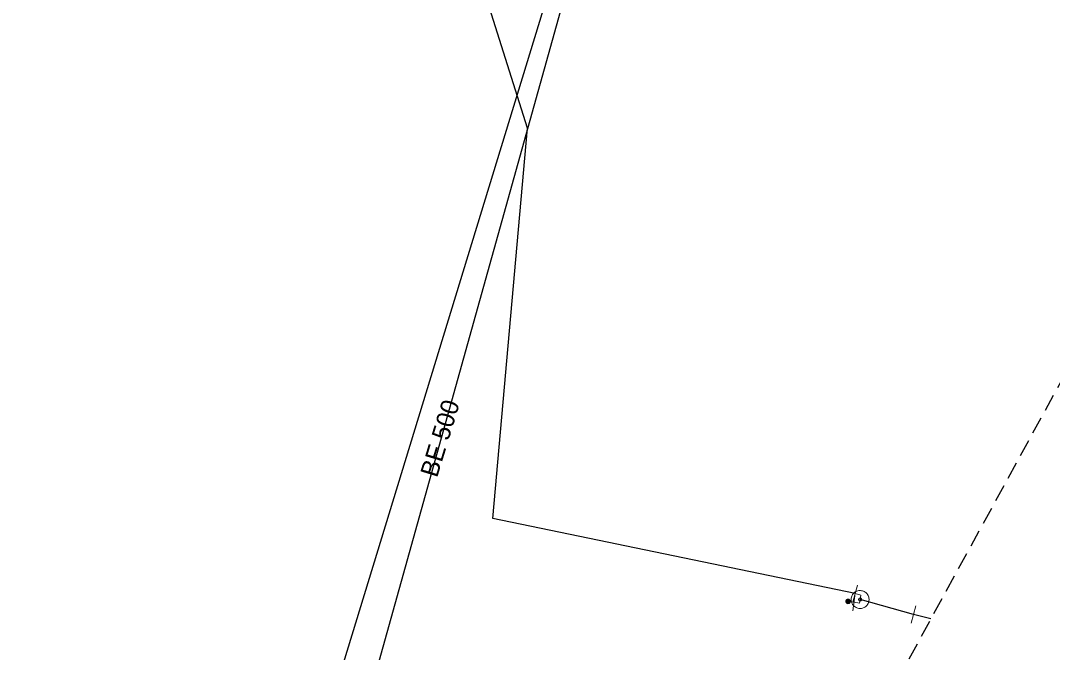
# Model space of a CAD drawing. Extents: x -725153 to -724843, y -978146 to -977794.
# Drawn here: x -724958 to -724900.4, y -978087.1 to -978051.8 of the extents above; entities that cross this region are included whole.
import ezdxf

# ---------------------------------------------------------------- set-up
doc = ezdxf.new("R2010")
doc.units = 0
doc.header["$LTSCALE"] = 0.32
doc.linetypes.add('MEDIUM_DASHED', pattern=[4.5, 3, -1.5])
doc.layers.add('1', color=7, linetype='Continuous')
for name, color, linetype, lineweight in [('14', 7, 'Continuous', 25), ('17', 7, 'Continuous', 25), ('34', 7, 'Continuous', 13), ('47', 7, 'Continuous', 13), ('63', 7, 'MEDIUM_DASHED', 25), ('9', 7, 'Continuous', 13)]:
    doc.layers.add(name, color=color, linetype=linetype, lineweight=lineweight)

msp = doc.modelspace()

# ---------------------------------------------------------------- linework, layer by layer
at = {"layer": '14'}
for p, q in [((-724927.944, -978048.326), (-724943.585, -978099.465)), ((-724927.274, -978049.14), (-724941.044, -978098.504))]:
    msp.add_line(p, q, dxfattribs=at)
at = {"layer": '14', "lineweight": 13}
for points in [[(-724911.375, -978083.783), (-724911.07, -978083.868), (-724911.108, -978084.11)], [(-724911.108, -978084.11), (-724911.147, -978084.309), (-724911.448, -978084.252), (-724911.778, -978084.216)]]:
    msp.add_lwpolyline(points, dxfattribs=at)
at = {"layer": '17'}
for points in [[(-724911.375, -978083.783), (-724931.616, -978079.579), (-724929.686, -978057.78), (-724935.405, -978039.66), (-724932.296, -977965.921)], [(-724907.151, -978085.183), (-724908.121, -978084.951), (-724911.108, -978084.11)]]:
    msp.add_lwpolyline(points, dxfattribs=at)
at = {"layer": '34'}
for p, q in [((-724911.245, -978083.3), (-724911.505, -978084.265)), ((-724911.379, -978083.756), (-724911.517, -978084.747)), ((-724907.986, -978084.469), (-724908.256, -978085.432))]:
    msp.add_line(p, q, dxfattribs=at)
at = {"layer": '47'}
for points in [[(-724910.608, -978084.137), (-724910.608, -978084.085), (-724910.613, -978084.033), (-724910.625, -978083.982), (-724910.64, -978083.932), (-724910.661, -978083.884), (-724910.688, -978083.838), (-724910.719, -978083.797), (-724910.753, -978083.758), (-724910.792, -978083.722), (-724910.834, -978083.691), (-724910.879, -978083.664), (-724910.927, -978083.644), (-724910.977, -978083.627), (-724911.028, -978083.616), (-724911.08, -978083.61), (-724911.132, -978083.61), (-724911.184, -978083.615), (-724911.236, -978083.627), (-724911.285, -978083.642), (-724911.333, -978083.663), (-724911.379, -978083.69), (-724911.421, -978083.721), (-724911.46, -978083.755), (-724911.496, -978083.794), (-724911.526, -978083.836), (-724911.553, -978083.881), (-724911.574, -978083.929), (-724911.59, -978083.979), (-724911.601, -978084.03), (-724911.607, -978084.082), (-724911.607, -978084.134), (-724911.602, -978084.186), (-724911.591, -978084.238), (-724911.575, -978084.287), (-724911.554, -978084.335), (-724911.528, -978084.381), (-724911.497, -978084.423), (-724911.463, -978084.462), (-724911.423, -978084.498), (-724911.381, -978084.528), (-724911.336, -978084.555), (-724911.289, -978084.576), (-724911.238, -978084.592), (-724911.187, -978084.603), (-724911.135, -978084.609), (-724911.083, -978084.609), (-724911.031, -978084.604), (-724910.98, -978084.593), (-724910.93, -978084.577), (-724910.882, -978084.556), (-724910.836, -978084.53), (-724910.795, -978084.499), (-724910.756, -978084.465), (-724910.72, -978084.425), (-724910.689, -978084.383), (-724910.662, -978084.338), (-724910.642, -978084.291), (-724910.625, -978084.24), (-724910.614, -978084.189)], [(-724911.026, -978084.114), (-724911.025, -978084.105), (-724911.027, -978084.097), (-724911.028, -978084.089), (-724911.031, -978084.081), (-724911.034, -978084.072), (-724911.039, -978084.065), (-724911.044, -978084.058), (-724911.049, -978084.052), (-724911.056, -978084.046), (-724911.063, -978084.041), (-724911.07, -978084.036), (-724911.078, -978084.033), (-724911.086, -978084.031), (-724911.094, -978084.028), (-724911.103, -978084.028), (-724911.112, -978084.027), (-724911.12, -978084.029), (-724911.128, -978084.03), (-724911.136, -978084.033), (-724911.145, -978084.036), (-724911.152, -978084.041), (-724911.159, -978084.046), (-724911.165, -978084.051), (-724911.172, -978084.058), (-724911.176, -978084.065), (-724911.181, -978084.072), (-724911.184, -978084.08), (-724911.186, -978084.088), (-724911.189, -978084.096), (-724911.189, -978084.105), (-724911.19, -978084.114), (-724911.188, -978084.122), (-724911.187, -978084.13), (-724911.184, -978084.138), (-724911.181, -978084.147), (-724911.177, -978084.154), (-724911.171, -978084.161), (-724911.166, -978084.167), (-724911.159, -978084.174), (-724911.152, -978084.178), (-724911.145, -978084.183), (-724911.137, -978084.186), (-724911.129, -978084.188), (-724911.121, -978084.191), (-724911.112, -978084.191), (-724911.103, -978084.192), (-724911.095, -978084.19), (-724911.087, -978084.189), (-724911.079, -978084.186), (-724911.07, -978084.183), (-724911.063, -978084.179), (-724911.056, -978084.173), (-724911.05, -978084.168), (-724911.044, -978084.161), (-724911.039, -978084.154), (-724911.034, -978084.147), (-724911.031, -978084.139), (-724911.029, -978084.131), (-724911.026, -978084.123)]]:
    msp.add_lwpolyline(points, close=True, dxfattribs=at)
at = {"layer": '63'}
msp.add_lwpolyline([(-725126.038, -977904.704), (-725126.038, -977794.451), (-724874.829, -977812.594), (-724855.29, -977827.945), (-724842.73, -977919.358), (-724859.477, -977998.21), (-724911.114, -978092.413), (-724961.356, -978146.144), (-725152.554, -978126.605)], close=True, dxfattribs=at)
at = {"layer": '9'}
for points in [[(-724911.904, -978084.216), (-724911.904, -978084.229), (-724911.902, -978084.242), (-724911.899, -978084.255), (-724911.894, -978084.267), (-724911.888, -978084.279), (-724911.881, -978084.29), (-724911.873, -978084.3), (-724911.863, -978084.31), (-724911.853, -978084.318), (-724911.842, -978084.325), (-724911.83, -978084.331), (-724911.818, -978084.336), (-724911.805, -978084.339), (-724911.792, -978084.341), (-724911.779, -978084.343), (-724911.766, -978084.342), (-724911.753, -978084.34), (-724911.74, -978084.337), (-724911.728, -978084.332), (-724911.716, -978084.326), (-724911.705, -978084.319), (-724911.695, -978084.311), (-724911.685, -978084.301), (-724911.677, -978084.291), (-724911.67, -978084.28), (-724911.664, -978084.268), (-724911.659, -978084.256), (-724911.656, -978084.243), (-724911.654, -978084.23), (-724911.652, -978084.217), (-724911.653, -978084.204), (-724911.655, -978084.191), (-724911.658, -978084.178), (-724911.663, -978084.166), (-724911.669, -978084.154), (-724911.676, -978084.143), (-724911.684, -978084.133), (-724911.694, -978084.123), (-724911.704, -978084.115), (-724911.715, -978084.108), (-724911.727, -978084.102), (-724911.739, -978084.097), (-724911.752, -978084.094), (-724911.765, -978084.092), (-724911.778, -978084.091), (-724911.791, -978084.091), (-724911.804, -978084.093), (-724911.817, -978084.096), (-724911.829, -978084.101), (-724911.841, -978084.107), (-724911.852, -978084.114), (-724911.862, -978084.122), (-724911.872, -978084.132), (-724911.88, -978084.142), (-724911.887, -978084.153), (-724911.893, -978084.165), (-724911.898, -978084.177), (-724911.901, -978084.19), (-724911.903, -978084.203)], [(-724911.884, -978084.216), (-724911.885, -978084.227), (-724911.883, -978084.238), (-724911.88, -978084.249), (-724911.876, -978084.259), (-724911.871, -978084.269), (-724911.865, -978084.278), (-724911.858, -978084.287), (-724911.85, -978084.295), (-724911.841, -978084.302), (-724911.832, -978084.308), (-724911.822, -978084.313), (-724911.812, -978084.317), (-724911.801, -978084.32), (-724911.79, -978084.323), (-724911.779, -978084.323), (-724911.768, -978084.323), (-724911.757, -978084.321), (-724911.746, -978084.318), (-724911.736, -978084.314), (-724911.726, -978084.309), (-724911.717, -978084.303), (-724911.708, -978084.296), (-724911.7, -978084.288), (-724911.693, -978084.279), (-724911.687, -978084.27), (-724911.682, -978084.26), (-724911.678, -978084.25), (-724911.675, -978084.239), (-724911.673, -978084.228), (-724911.672, -978084.217), (-724911.672, -978084.206), (-724911.674, -978084.195), (-724911.677, -978084.184), (-724911.681, -978084.174), (-724911.686, -978084.164), (-724911.692, -978084.155), (-724911.699, -978084.146), (-724911.707, -978084.138), (-724911.716, -978084.131), (-724911.725, -978084.125), (-724911.735, -978084.12), (-724911.745, -978084.116), (-724911.756, -978084.113), (-724911.767, -978084.111), (-724911.778, -978084.111), (-724911.789, -978084.11), (-724911.8, -978084.112), (-724911.811, -978084.115), (-724911.821, -978084.119), (-724911.831, -978084.124), (-724911.84, -978084.13), (-724911.849, -978084.137), (-724911.857, -978084.145), (-724911.864, -978084.154), (-724911.87, -978084.163), (-724911.875, -978084.173), (-724911.879, -978084.183), (-724911.882, -978084.194), (-724911.884, -978084.205)], [(-724911.865, -978084.216), (-724911.865, -978084.225), (-724911.864, -978084.234), (-724911.861, -978084.243), (-724911.858, -978084.251), (-724911.854, -978084.259), (-724911.849, -978084.267), (-724911.843, -978084.274), (-724911.837, -978084.28), (-724911.83, -978084.286), (-724911.822, -978084.291), (-724911.814, -978084.295), (-724911.806, -978084.298), (-724911.797, -978084.301), (-724911.788, -978084.302), (-724911.779, -978084.304), (-724911.77, -978084.303), (-724911.761, -978084.302), (-724911.752, -978084.299), (-724911.744, -978084.296), (-724911.736, -978084.292), (-724911.728, -978084.287), (-724911.721, -978084.281), (-724911.715, -978084.275), (-724911.709, -978084.268), (-724911.704, -978084.26), (-724911.7, -978084.252), (-724911.697, -978084.244), (-724911.694, -978084.235), (-724911.693, -978084.226), (-724911.691, -978084.217), (-724911.692, -978084.208), (-724911.693, -978084.199), (-724911.696, -978084.19), (-724911.699, -978084.182), (-724911.703, -978084.174), (-724911.708, -978084.166), (-724911.714, -978084.159), (-724911.72, -978084.153), (-724911.727, -978084.147), (-724911.735, -978084.142), (-724911.743, -978084.138), (-724911.751, -978084.135), (-724911.76, -978084.132), (-724911.769, -978084.131), (-724911.778, -978084.13), (-724911.787, -978084.13), (-724911.796, -978084.131), (-724911.805, -978084.134), (-724911.813, -978084.137), (-724911.821, -978084.141), (-724911.829, -978084.146), (-724911.836, -978084.152), (-724911.842, -978084.158), (-724911.848, -978084.165), (-724911.853, -978084.173), (-724911.857, -978084.181), (-724911.86, -978084.189), (-724911.863, -978084.198), (-724911.864, -978084.207)], [(-724911.845, -978084.216), (-724911.845, -978084.223), (-724911.844, -978084.23), (-724911.843, -978084.237), (-724911.84, -978084.243), (-724911.837, -978084.249), (-724911.833, -978084.255), (-724911.829, -978084.261), (-724911.824, -978084.266), (-724911.818, -978084.27), (-724911.812, -978084.274), (-724911.806, -978084.277), (-724911.8, -978084.28), (-724911.793, -978084.281), (-724911.786, -978084.284), (-724911.779, -978084.284), (-724911.772, -978084.284), (-724911.765, -978084.282), (-724911.758, -978084.281), (-724911.752, -978084.278), (-724911.745, -978084.275), (-724911.74, -978084.271), (-724911.734, -978084.267), (-724911.729, -978084.262), (-724911.725, -978084.256), (-724911.721, -978084.25), (-724911.718, -978084.244), (-724911.715, -978084.238), (-724911.713, -978084.231), (-724911.712, -978084.224), (-724911.711, -978084.217), (-724911.711, -978084.21), (-724911.712, -978084.203), (-724911.714, -978084.196), (-724911.717, -978084.19), (-724911.72, -978084.183), (-724911.724, -978084.178), (-724911.728, -978084.172), (-724911.733, -978084.167), (-724911.739, -978084.163), (-724911.744, -978084.159), (-724911.751, -978084.156), (-724911.757, -978084.153), (-724911.764, -978084.151), (-724911.771, -978084.15), (-724911.778, -978084.15), (-724911.785, -978084.15), (-724911.792, -978084.15), (-724911.799, -978084.152), (-724911.805, -978084.155), (-724911.811, -978084.158), (-724911.817, -978084.162), (-724911.823, -978084.166), (-724911.828, -978084.171), (-724911.832, -978084.177), (-724911.836, -978084.182), (-724911.839, -978084.189), (-724911.842, -978084.195), (-724911.843, -978084.202), (-724911.845, -978084.209)], [(-724911.825, -978084.216), (-724911.825, -978084.221), (-724911.825, -978084.226), (-724911.824, -978084.231), (-724911.822, -978084.235), (-724911.82, -978084.24), (-724911.817, -978084.244), (-724911.814, -978084.247), (-724911.81, -978084.251), (-724911.807, -978084.254), (-724911.803, -978084.257), (-724911.798, -978084.259), (-724911.794, -978084.261), (-724911.789, -978084.262), (-724911.784, -978084.264), (-724911.779, -978084.264), (-724911.774, -978084.264), (-724911.769, -978084.263), (-724911.764, -978084.262), (-724911.76, -978084.26), (-724911.755, -978084.258), (-724911.751, -978084.255), (-724911.747, -978084.252), (-724911.744, -978084.248), (-724911.741, -978084.245), (-724911.738, -978084.241), (-724911.736, -978084.236), (-724911.734, -978084.232), (-724911.733, -978084.227), (-724911.732, -978084.222), (-724911.731, -978084.217), (-724911.731, -978084.212), (-724911.732, -978084.207), (-724911.733, -978084.202), (-724911.735, -978084.198), (-724911.737, -978084.193), (-724911.74, -978084.189), (-724911.743, -978084.185), (-724911.746, -978084.182), (-724911.75, -978084.179), (-724911.754, -978084.176), (-724911.759, -978084.174), (-724911.763, -978084.172), (-724911.768, -978084.171), (-724911.773, -978084.17), (-724911.778, -978084.17), (-724911.783, -978084.17), (-724911.788, -978084.171), (-724911.793, -978084.171), (-724911.797, -978084.173), (-724911.802, -978084.175), (-724911.806, -978084.178), (-724911.809, -978084.181), (-724911.813, -978084.184), (-724911.816, -978084.188), (-724911.819, -978084.192), (-724911.821, -978084.197), (-724911.823, -978084.201), (-724911.824, -978084.206), (-724911.825, -978084.211)], [(-724911.805, -978084.216), (-724911.805, -978084.219), (-724911.806, -978084.222), (-724911.805, -978084.224), (-724911.804, -978084.227), (-724911.803, -978084.23), (-724911.801, -978084.232), (-724911.799, -978084.234), (-724911.797, -978084.236), (-724911.795, -978084.238), (-724911.793, -978084.24), (-724911.79, -978084.242), (-724911.787, -978084.243), (-724911.785, -978084.243), (-724911.782, -978084.244), (-724911.779, -978084.244), (-724911.776, -978084.244), (-724911.773, -978084.244), (-724911.77, -978084.243), (-724911.768, -978084.242), (-724911.765, -978084.241), (-724911.763, -978084.239), (-724911.76, -978084.237), (-724911.758, -978084.235), (-724911.757, -978084.233), (-724911.755, -978084.231), (-724911.754, -978084.228), (-724911.752, -978084.225), (-724911.752, -978084.223), (-724911.751, -978084.22), (-724911.75, -978084.217), (-724911.751, -978084.214), (-724911.751, -978084.211), (-724911.752, -978084.208), (-724911.753, -978084.206), (-724911.754, -978084.203), (-724911.756, -978084.201), (-724911.757, -978084.198), (-724911.759, -978084.196), (-724911.762, -978084.195), (-724911.764, -978084.193), (-724911.767, -978084.192), (-724911.769, -978084.191), (-724911.772, -978084.19), (-724911.775, -978084.19), (-724911.778, -978084.189), (-724911.781, -978084.19), (-724911.784, -978084.189), (-724911.786, -978084.191), (-724911.789, -978084.191), (-724911.792, -978084.192), (-724911.794, -978084.194), (-724911.796, -978084.195), (-724911.798, -978084.197), (-724911.8, -978084.2), (-724911.802, -978084.202), (-724911.803, -978084.205), (-724911.804, -978084.207), (-724911.805, -978084.21), (-724911.805, -978084.213)], [(-724911.786, -978084.216), (-724911.786, -978084.218), (-724911.786, -978084.218), (-724911.785, -978084.218), (-724911.785, -978084.22), (-724911.786, -978084.221), (-724911.784, -978084.221), (-724911.784, -978084.221), (-724911.784, -978084.223), (-724911.784, -978084.223), (-724911.783, -978084.224), (-724911.781, -978084.224), (-724911.781, -978084.224), (-724911.781, -978084.225), (-724911.779, -978084.225), (-724911.779, -978084.225), (-724911.778, -978084.225), (-724911.777, -978084.225), (-724911.777, -978084.224), (-724911.776, -978084.224), (-724911.774, -978084.224), (-724911.774, -978084.223), (-724911.774, -978084.223), (-724911.773, -978084.222), (-724911.773, -978084.222), (-724911.771, -978084.221), (-724911.771, -978084.22), (-724911.77, -978084.219), (-724911.77, -978084.219), (-724911.77, -978084.218), (-724911.77, -978084.217), (-724911.77, -978084.216), (-724911.77, -978084.215), (-724911.77, -978084.215), (-724911.771, -978084.214), (-724911.771, -978084.213), (-724911.772, -978084.212), (-724911.772, -978084.212), (-724911.773, -978084.211), (-724911.773, -978084.211), (-724911.774, -978084.21), (-724911.775, -978084.21), (-724911.776, -978084.209), (-724911.776, -978084.209), (-724911.777, -978084.209), (-724911.778, -978084.209), (-724911.779, -978084.209), (-724911.78, -978084.209), (-724911.78, -978084.209), (-724911.781, -978084.21), (-724911.782, -978084.209), (-724911.783, -978084.211), (-724911.783, -978084.211), (-724911.784, -978084.211), (-724911.784, -978084.211), (-724911.785, -978084.213), (-724911.785, -978084.214), (-724911.785, -978084.215), (-724911.786, -978084.215), (-724911.786, -978084.216)]]:
    msp.add_lwpolyline(points, close=True, dxfattribs=at)

# ---------------------------------------------------------------- texts
at = {"layer": '1'}
msp.add_text('BE 500', height=1, rotation=73, dxfattribs=at).set_placement((-724934.743, -978077.344))

doc.saveas('drawing.dxf')
